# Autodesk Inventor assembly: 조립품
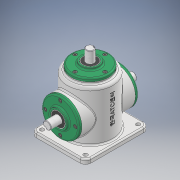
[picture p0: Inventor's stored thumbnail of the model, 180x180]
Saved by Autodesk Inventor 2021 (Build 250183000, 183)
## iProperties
Created: 2021-02
Part Number: 조립품
Document SubType Name: Assembly
Designer: 201-09
Author: 201-09
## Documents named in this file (16)
- C:\Users\201-09\Desktop\710215V1002\조립품.iam
- C:\Users\201-09\Desktop\710215V1002\본체.ipt
- C:\Users\201-09\Desktop\710215V1002\커버.ipt
- C:\Users\201-09\Desktop\710215V1002\베어링 6203.ipt
- C:\Users\201-09\Desktop\710215V1002\오일 실.ipt
- 오일 실.ipt
- C:\Users\201-09\Desktop\710215V1002\메인 축.ipt
- 메인 축.ipt
- C:\Users\201-09\Desktop\710215V1002\키 5x5.ipt
- C:\Users\201-09\Desktop\710215V1002\메인 베벨기어.ipt
- C:\Users\201-09\Desktop\710215V1002\서브 축.ipt
- 서브 축.ipt
- C:\Users\201-09\Desktop\710215V1002\키 4x4.ipt
- C:\Users\201-09\Desktop\710215V1002\서브 베벨기어.ipt
- C:\Users\201-09\Desktop\710215V1002\볼트 M4.ipt
- 볼트 M4.ipt
